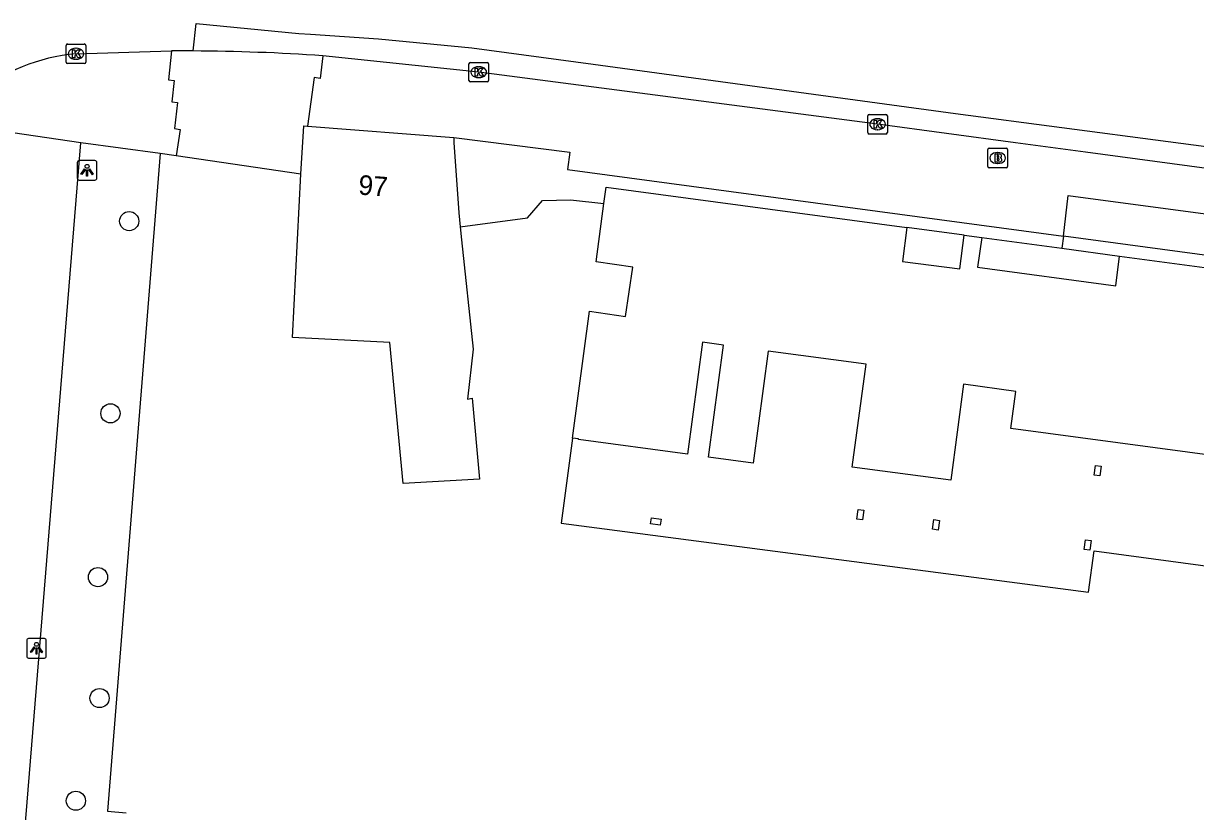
# Model space of a CAD drawing. Extents: x 159961 to 160856, y 382704 to 383353.
# Drawn here: x 160457.1 to 160516.9, y 383273.9 to 383314.1 of the extents above; entities that cross this region are included whole.
import ezdxf

# ---------------------------------------------------------------- set-up
doc = ezdxf.new("R2010")
doc.units = 0
for name, color, linetype in [('IMGEO_Boom', 7, 'Continuous'), ('IMGEO_Brandkraan', 7, 'Continuous'), ('IMGEO_Erf', 7, 'Continuous'), ('IMGEO_Groenvoorziening', 7, 'Continuous'), ('IMGEO_Kolk', 7, 'Continuous'), ('IMGEO_Lichtpunt', 7, 'Continuous'), ('IMGEO_Pand', 7, 'Continuous'), ('IMGEO_Pand_nummerreeks', 7, 'Continuous'), ('IMGEO_Pand_overbouw', 7, 'Continuous'), ('IMGEO_Rijbaan_lokaal_gesloten', 7, 'Continuous'), ('IMGEO_Voetpad_open', 7, 'Continuous')]:
    doc.layers.add(name, color=color, linetype=linetype)

msp = doc.modelspace()

# ---------------------------------------------------------------- linework, layer by layer
at = {"layer": 'IMGEO_Boom'}
for centre in [(160462.46, 383304.019), (160461.502, 383294.215), (160460.865, 383285.865), (160460.948, 383279.694), (160459.738, 383274.458)]:
    msp.add_circle(centre, 0.489, dxfattribs=at)
at = {"layer": 'IMGEO_Brandkraan'}
for p, q in [((160506.278, 383306.813), (160506.278, 383307.665)), ((160506.353, 383307.739), (160507.205, 383307.739)), ((160506.766, 383307.519), (160506.791, 383307.519)), ((160507.279, 383307.665), (160507.279, 383306.813)), ((160506.789, 383306.959), (160506.764, 383306.959)), ((160507.205, 383306.739), (160506.353, 383306.739))]:
    msp.add_line(p, q, dxfattribs=at)
for points in [[(160506.278, 383306.813), (160506.278, 383307.665)], [(160506.353, 383307.739), (160507.205, 383307.739)], [(160506.626, 383307.439), (160506.626, 383307.039), (160506.839, 383307.039)], [(160506.857, 383307.439), (160506.626, 383307.439)], [(160507.279, 383307.665), (160507.279, 383306.813)], [(160506.805, 383307.358), (160506.751, 383307.358), (160506.751, 383307.282)], [(160506.751, 383307.282), (160506.804, 383307.282)], [(160506.813, 383307.206), (160506.751, 383307.206), (160506.751, 383307.125)], [(160506.751, 383307.125), (160506.813, 383307.125)], [(160507.205, 383306.739), (160506.353, 383306.739)]]:
    msp.add_lwpolyline(points, dxfattribs=at)
for centre, radius, start, end in [((160506.355, 383307.663), 0.0765, 91.55205, 178.44795), ((160506.355, 383307.663), 0.0765, 91.55205, 178.44795), ((160506.861, 383307.294), 0.145, 59.4692, 91.53667), ((160506.886, 383307.341), 0.0922, 285.51372, 58.15012), ((160507.203, 383307.663), 0.0765, 1.55205, 88.44795), ((160507.203, 383307.663), 0.0765, 1.55205, 88.44795), ((160506.355, 383306.815), 0.0765, 181.55205, 268.44795), ((160506.355, 383306.815), 0.0765, 181.55205, 268.44795), ((160506.806, 383307.32), 0.0379, 267.82845, 90.93552), ((160506.814, 383307.165), 0.0404, 269.87594, 90.50774), ((160506.845, 383307.29), 0.251, 268.66757, 293.53466), ((160506.891, 383307.149), 0.105, 301.31148, 78.98903), ((160507.203, 383306.815), 0.0765, 271.55205, 358.44795), ((160507.203, 383306.815), 0.0765, 271.55205, 358.44795)]:
    msp.add_arc(centre, radius, start, end, dxfattribs=at)
for centre, major_axis, ratio, start_param, end_param in [((160506.765, 383307.239), (-0.387, 0.002), 0.722429, 4.712389, 7.853982), ((160506.79, 383307.239), (-0.39, 0.002), 0.717154, 1.570796, 4.712389)]:
    msp.add_ellipse(centre, major_axis=major_axis, ratio=ratio, start_param=start_param, end_param=end_param, dxfattribs=at)
at = {"layer": 'IMGEO_Erf'}
for points in [[(160479.346, 383303.733), (160482.781, 383304.192), (160483.543, 383305.07), (160484.987, 383305.105), (160486.689, 383304.914)], [(160505.964, 383303.179), (160510.058, 383302.632)]]:
    msp.add_lwpolyline(points, dxfattribs=at)
at = {"layer": 'IMGEO_Groenvoorziening'}
msp.add_lwpolyline([(160464.042, 383307.463), (160461.346, 383273.927), (160462.297, 383273.845)], dxfattribs=at)
at = {"layer": 'IMGEO_Kolk'}
for p, q in [((160459.242, 383312.127), (160459.242, 383312.979)), ((160459.317, 383313.053), (160460.169, 383313.053)), ((160459.73, 383312.833), (160459.755, 383312.833)), ((160460.243, 383312.979), (160460.243, 383312.127)), ((160459.753, 383312.273), (160459.728, 383312.273)), ((160460.169, 383312.053), (160459.317, 383312.053)), ((160479.797, 383311.19), (160479.797, 383312.042)), ((160479.872, 383312.116), (160480.724, 383312.116)), ((160480.285, 383311.896), (160480.31, 383311.896)), ((160480.798, 383312.042), (160480.798, 383311.19)), ((160480.724, 383311.116), (160479.872, 383311.116)), ((160480.308, 383311.336), (160480.283, 383311.336)), ((160500.15, 383308.537), (160500.15, 383309.389)), ((160500.225, 383309.463), (160501.077, 383309.463)), ((160500.638, 383309.243), (160500.663, 383309.243)), ((160501.151, 383309.389), (160501.151, 383308.537)), ((160500.661, 383308.683), (160500.636, 383308.683)), ((160501.077, 383308.463), (160500.225, 383308.463))]:
    msp.add_line(p, q, dxfattribs=at)
for points in [[(160459.242, 383312.127), (160459.242, 383312.979)], [(160459.317, 383313.053), (160460.169, 383313.053)], [(160460.243, 383312.979), (160460.243, 383312.127)], [(160459.563, 383312.753), (160459.686, 383312.753), (160459.686, 383312.602), (160459.816, 383312.753), (160459.98, 383312.753), (160459.834, 383312.602), (160459.987, 383312.353), (160459.835, 383312.353), (160459.75, 383312.517), (160459.686, 383312.45), (160459.686, 383312.353), (160459.563, 383312.353), (160459.563, 383312.753)], [(160460.169, 383312.053), (160459.317, 383312.053)], [(160479.797, 383311.19), (160479.797, 383312.042)], [(160479.872, 383312.116), (160480.724, 383312.116)], [(160480.118, 383311.816), (160480.241, 383311.816), (160480.241, 383311.665), (160480.371, 383311.816), (160480.535, 383311.816), (160480.389, 383311.665), (160480.542, 383311.416), (160480.39, 383311.416), (160480.305, 383311.58), (160480.241, 383311.513), (160480.241, 383311.416), (160480.118, 383311.416), (160480.118, 383311.816)], [(160480.798, 383312.042), (160480.798, 383311.19)], [(160480.724, 383311.116), (160479.872, 383311.116)], [(160500.15, 383308.537), (160500.15, 383309.389)], [(160500.225, 383309.463), (160501.077, 383309.463)], [(160501.151, 383309.389), (160501.151, 383308.537)], [(160500.471, 383309.163), (160500.594, 383309.163), (160500.594, 383309.012), (160500.724, 383309.163), (160500.888, 383309.163), (160500.742, 383309.012), (160500.895, 383308.763), (160500.743, 383308.763), (160500.658, 383308.927), (160500.594, 383308.86), (160500.594, 383308.763), (160500.471, 383308.763), (160500.471, 383309.163)], [(160501.077, 383308.463), (160500.225, 383308.463)]]:
    msp.add_lwpolyline(points, dxfattribs=at)
for centre, start, end in [((160459.319, 383312.977), 91.55205, 178.44795), ((160459.319, 383312.977), 91.55205, 178.44795), ((160460.167, 383312.977), 1.55205, 88.44795), ((160460.167, 383312.977), 1.55205, 88.44795), ((160459.319, 383312.129), 181.55205, 268.44795), ((160459.319, 383312.129), 181.55205, 268.44795), ((160460.167, 383312.129), 271.55205, 358.44795), ((160460.167, 383312.129), 271.55205, 358.44795), ((160479.874, 383312.04), 91.55205, 178.44795), ((160479.874, 383312.04), 91.55205, 178.44795), ((160480.722, 383312.04), 1.55205, 88.44795), ((160480.722, 383312.04), 1.55205, 88.44795), ((160479.874, 383311.192), 181.55205, 268.44795), ((160479.874, 383311.192), 181.55205, 268.44795), ((160480.722, 383311.192), 271.55205, 358.44795), ((160480.722, 383311.192), 271.55205, 358.44795), ((160500.227, 383309.387), 91.55205, 178.44795), ((160500.227, 383309.387), 91.55205, 178.44795), ((160501.075, 383309.387), 1.55205, 88.44795), ((160501.075, 383309.387), 1.55205, 88.44795), ((160500.227, 383308.539), 181.55205, 268.44795), ((160500.227, 383308.539), 181.55205, 268.44795), ((160501.075, 383308.539), 271.55205, 358.44795), ((160501.075, 383308.539), 271.55205, 358.44795)]:
    msp.add_arc(centre, 0.0765, start, end, dxfattribs=at)
for centre, major_axis, ratio, start_param, end_param in [((160459.729, 383312.553), (-0.387, 0.002), 0.722429, 4.712389, 7.853982), ((160459.754, 383312.553), (-0.39, 0.002), 0.717154, 1.570796, 4.712389), ((160480.284, 383311.616), (-0.387, 0.002), 0.722429, 4.712389, 7.853982), ((160480.309, 383311.616), (-0.39, 0.002), 0.717154, 1.570796, 4.712389), ((160500.637, 383308.963), (-0.387, 0.002), 0.722429, 4.712389, 7.853982), ((160500.662, 383308.963), (-0.39, 0.002), 0.717154, 1.570796, 4.712389)]:
    msp.add_ellipse(centre, major_axis=major_axis, ratio=ratio, start_param=start_param, end_param=end_param, dxfattribs=at)
at = {"layer": 'IMGEO_Lichtpunt'}
for p, q in [((160459.812, 383307.015), (160459.812, 383306.208)), ((160459.812, 383307.015), (160459.812, 383306.208)), ((160460.714, 383307.11), (160459.906, 383307.11)), ((160460.714, 383307.11), (160459.906, 383307.11)), ((160460.808, 383306.208), (160460.808, 383307.015)), ((160460.808, 383306.208), (160460.808, 383307.015)), ((160459.906, 383306.114), (160460.714, 383306.114)), ((160459.906, 383306.114), (160460.714, 383306.114)), ((160457.231, 383282.636), (160457.231, 383281.829)), ((160457.231, 383282.636), (160457.231, 383281.829)), ((160458.133, 383282.731), (160457.325, 383282.731)), ((160458.133, 383282.731), (160457.325, 383282.731)), ((160458.227, 383281.829), (160458.227, 383282.636)), ((160458.227, 383281.829), (160458.227, 383282.636)), ((160457.325, 383281.735), (160458.133, 383281.735)), ((160457.325, 383281.735), (160458.133, 383281.735))]:
    msp.add_line(p, q, dxfattribs=at)
for points in [[(160460.186, 383306.679), (160460.225, 383306.651), (160460.037, 383306.389), (160459.999, 383306.416), (160460.186, 383306.679)], [(160460.288, 383306.631), (160460.335, 383306.631), (160460.335, 383306.309), (160460.288, 383306.309), (160460.288, 383306.631)], [(160460.398, 383306.651), (160460.436, 383306.678), (160460.623, 383306.416), (160460.584, 383306.388), (160460.398, 383306.651)], [(160457.605, 383282.3), (160457.644, 383282.272), (160457.456, 383282.01), (160457.418, 383282.037), (160457.605, 383282.3)], [(160457.817, 383282.272), (160457.855, 383282.299), (160458.042, 383282.037), (160458.003, 383282.009), (160457.817, 383282.272)], [(160457.707, 383282.252), (160457.754, 383282.252), (160457.754, 383281.93), (160457.707, 383281.93), (160457.707, 383282.252)]]:
    msp.add_lwpolyline(points, dxfattribs=at)
for centre in [(160460.311, 383306.813), (160457.73, 383282.434)]:
    msp.add_circle(centre, 0.0994, dxfattribs=at)
for centre, start, end in [((160459.906, 383307.015), 90, 180), ((160459.906, 383307.015), 90, 180), ((160460.714, 383307.015), 0, 90), ((160460.714, 383307.015), 0, 90), ((160459.906, 383306.208), 180, 270), ((160459.906, 383306.208), 180, 270), ((160460.714, 383306.208), 270, 0), ((160460.714, 383306.208), 270, 360), ((160457.325, 383282.636), 90, 180), ((160457.325, 383282.636), 90, 180), ((160458.133, 383282.636), 0, 90), ((160458.133, 383282.636), 0, 90), ((160457.325, 383281.829), 180, 270), ((160457.325, 383281.829), 180, 270), ((160458.133, 383281.829), 270, 0), ((160458.133, 383281.829), 270, 360)]:
    msp.add_arc(centre, 0.0946, start, end, dxfattribs=at)
at = {"layer": 'IMGEO_Pand'}
for points in [[(160471.211, 383306.42), (160471.379, 383308.882), (160471.562, 383308.868)], [(160471.562, 383308.868), (160479.033, 383308.293)], [(160479.033, 383308.293), (160479.02, 383308.026), (160479.276, 383304.445), (160479.346, 383303.733)], [(160479.346, 383303.733), (160479.412, 383303.066), (160480.011, 383297.488), (160479.724, 383294.942), (160479.965, 383294.982), (160480.336, 383290.852), (160476.439, 383290.639), (160475.765, 383297.825), (160470.786, 383298.077), (160471.211, 383306.42)], [(160486.689, 383304.914), (160486.801, 383305.747), (160502.144, 383303.691), (160501.922, 383301.967), (160504.846, 383301.592), (160505.065, 383303.3), (160505.964, 383303.179)], [(160567.263, 383285.442), (160507.452, 383293.44), (160507.714, 383295.33), (160505.036, 383295.702), (160504.384, 383290.809), (160499.356, 383291.477), (160500.061, 383296.72), (160495.069, 383297.391), (160494.302, 383291.676), (160492.022, 383291.982), (160492.79, 383297.698), (160491.716, 383297.842), (160490.948, 383292.127), (160485.392, 383292.878), (160485.396, 383292.908), (160485.079, 383292.951), (160485.951, 383299.429), (160487.794, 383299.157), (160488.166, 383301.67), (160486.29, 383301.947), (160486.689, 383304.914)], [(160505.964, 383303.179), (160505.754, 383301.665), (160512.803, 383300.721), (160512.989, 383302.24)], [(160512.989, 383302.24), (160521.422, 383301.112)], [(160511.701, 383291.062), (160511.768, 383291.558), (160512.066, 383291.517), (160511.999, 383291.022), (160511.701, 383291.062)], [(160489.067, 383288.587), (160489.107, 383288.884), (160489.602, 383288.817), (160489.562, 383288.52), (160489.067, 383288.587)], [(160499.883, 383288.781), (160499.585, 383288.821), (160499.652, 383289.316), (160499.95, 383289.276), (160499.883, 383288.781)], [(160503.75, 383288.264), (160503.453, 383288.304), (160503.52, 383288.799), (160503.817, 383288.759), (160503.75, 383288.264)], [(160511.188, 383287.269), (160511.255, 383287.765), (160511.552, 383287.725), (160511.485, 383287.23), (160511.188, 383287.269)]]:
    msp.add_lwpolyline(points, dxfattribs=at)
at = {"layer": 'IMGEO_Pand_overbouw'}
msp.add_lwpolyline([(160505.065, 383303.3), (160502.144, 383303.691), (160501.922, 383301.967), (160504.846, 383301.592)], close=True, dxfattribs=at)
msp.add_lwpolyline([(160567.263, 383285.442), (160507.452, 383293.44), (160507.714, 383295.33), (160505.036, 383295.702), (160504.384, 383290.809), (160499.356, 383291.477), (160500.061, 383296.72), (160495.069, 383297.391), (160494.302, 383291.676), (160492.022, 383291.982), (160492.79, 383297.698), (160491.716, 383297.842), (160490.948, 383292.127), (160485.392, 383292.878), (160485.396, 383292.908), (160485.079, 383292.951), (160484.496, 383288.616), (160511.416, 383285.088), (160511.698, 383287.201), (160518.648, 383286.272)], dxfattribs=at)
at = {"layer": 'IMGEO_Rijbaan_lokaal_gesloten'}
for points in [[(160465.717, 383312.698), (160465.869, 383314.101), (160471.121, 383313.593), (160471.711, 383313.553), (160475.178, 383313.319), (160479.948, 383312.866), (160486.143, 383312.03), (160504.619, 383309.508), (160531.757, 383305.943), (160561.582, 383301.939), (160581.264, 383299.361), (160581.134, 383298.127)], [(160459.743, 383312.553), (160464.623, 383312.699)], [(160581.134, 383298.127), (160574.879, 383298.991), (160547.702, 383302.642), (160541.716, 383303.446), (160511.254, 383307.538), (160507.697, 383308.016), (160500.651, 383308.963), (160480.298, 383311.616), (160472.343, 383312.455)]]:
    msp.add_lwpolyline(points, dxfattribs=at)
for centre, radius, start, end in [((160460.54, 383303.283), 9.304, 94.91596, 129.76377), ((160465.079, 383212.963), 99.737, 89.63339, 90.26186), ((160465.15, 383206.774), 105.925, 86.10617, 89.69322)]:
    msp.add_arc(centre, radius, start, end, dxfattribs=at)
at = {"layer": 'IMGEO_Voetpad_open'}
for points in [[(160464.623, 383312.699), (160464.457, 383311.224), (160464.762, 383311.186), (160464.635, 383310.112), (160464.921, 383310.074), (160464.771, 383308.741), (160465.053, 383308.696), (160464.848, 383307.352)], [(160472.343, 383312.455), (160472.204, 383311.293), (160471.895, 383311.34), (160471.562, 383308.868)], [(160452.266, 383213.376), (160452.763, 383219.455), (160459.993, 383308.019)], [(160459.993, 383308.019), (160456.522, 383308.527)], [(160464.042, 383307.463), (160459.993, 383308.019)], [(160479.033, 383308.293), (160484.942, 383307.538), (160484.834, 383306.647), (160510.132, 383303.244)], [(160464.848, 383307.352), (160464.042, 383307.463)], [(160471.211, 383306.42), (160464.848, 383307.352)], [(160510.132, 383303.244), (160510.384, 383305.328), (160536.64, 383301.822)], [(160510.132, 383303.244), (160510.058, 383302.632)], [(160586.429, 383292.981), (160510.132, 383303.244)], [(160510.058, 383302.632), (160512.989, 383302.24)]]:
    msp.add_lwpolyline(points, dxfattribs=at)

# ---------------------------------------------------------------- texts
at = {"layer": 'IMGEO_Pand_nummerreeks'}
msp.add_text('97', height=1, rotation=355.59958, dxfattribs=at).set_placement((160474.13, 383305.381))

doc.saveas('drawing.dxf')
